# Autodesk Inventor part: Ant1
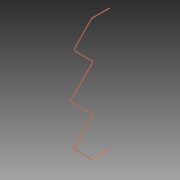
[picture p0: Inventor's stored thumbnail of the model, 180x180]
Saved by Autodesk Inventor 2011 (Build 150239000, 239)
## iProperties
Created: 2014-02
Part Number: Ant1
Document SubType Name: Modeling
Designer: Evgeny
Density: 1 g/cm^3
Author: Evgeny
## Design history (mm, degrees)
sketch "Эскиз1"
  geometry: C1 r 1.5 at (0, 0); 1 further point
  constraints: 1 centre point, 1 coincident
  dimensions: "d0" = 3 diameter of C1
sketch "Эскиз2"
  geometry: L1 (2.843, 2.833)-(93.494, 93.171); L2 (93.498, 98.833)-(17.075, 175.211); L3 (17.034, 180.829)-(86.998, 252.788); L4 (89.866, 254)-(162.176, 254); L5 (2.843, -2.833)-(93.494, -93.171); L6 (93.498, -98.833)-(17.075, -175.211); L7 (17.034, -180.829)-(86.998, -252.788); L8 (89.866, -254)-(162.176, -254); A1 r 4 centre (89.866, 250) between (89.866, 254) and (86.998, 252.788); A2 r 4 centre (19.902, 178.04) between (17.034, 180.829) and (17.075, 175.211); A3 r 4 centre (90.67, 96.004) between (93.494, 93.171) and (93.498, 98.833); A4 r 4 centre (90.67, -96.004) between (93.498, -98.833) and (93.494, -93.171); A5 r 4 centre (19.902, -178.04) between (17.075, -175.211) and (17.034, -180.829); A6 r 4 centre (89.866, -250) between (86.998, -252.788) and (89.866, -254); A7 r 4 centre (5.667, 0) between (2.843, 2.833) and (2.843, -2.833); 7 further points
  constraints: 16 end point, 14 point on circle, 14 point on line, 14 tangent, 7 centre point, 6 equal radius, 1 horizontal, 1 parallel
  dimensions: "d40" = 254 distance from line of L4 point (0, 0); "d41" = 508 distance between parallel lines of L8 L4; "d42" = 136 distance of point (0, 0) point (96.333, 96); "d43" = 136 distance of point (0, 0) point (96.333, -96); "d44" = 96 vertical distance of point (96.333, 96) point (0, 0); "d45" = 96 vertical distance of point (96.333, -96) point (0, 0); "d46" = 178 vertical distance of point (14.284, -178) point (0, 0); "d47" = 178 vertical distance of point (14.284, 178) point (0, 0); "d48" = 116 distance of point (96.333, 96) point (14.284, 178); "d49" = 116 distance of point (96.333, -96) point (14.284, -178); "d50" = 106 distance of point (14.284, 178) point (88.176, 254); "d51" = 106 distance of point (14.284, -178) point (88.176, -254); "d52" = 74 distance of point (88.176, 254) L4.end; "d53" = 74 distance of point (88.176, -254) L8.end; "d54" = 4 radius of A1
feature "Сдвиг1" sketch "Эскиз1", "Эскиз2" dims "d4" = 0
node "Твердое тело2"
